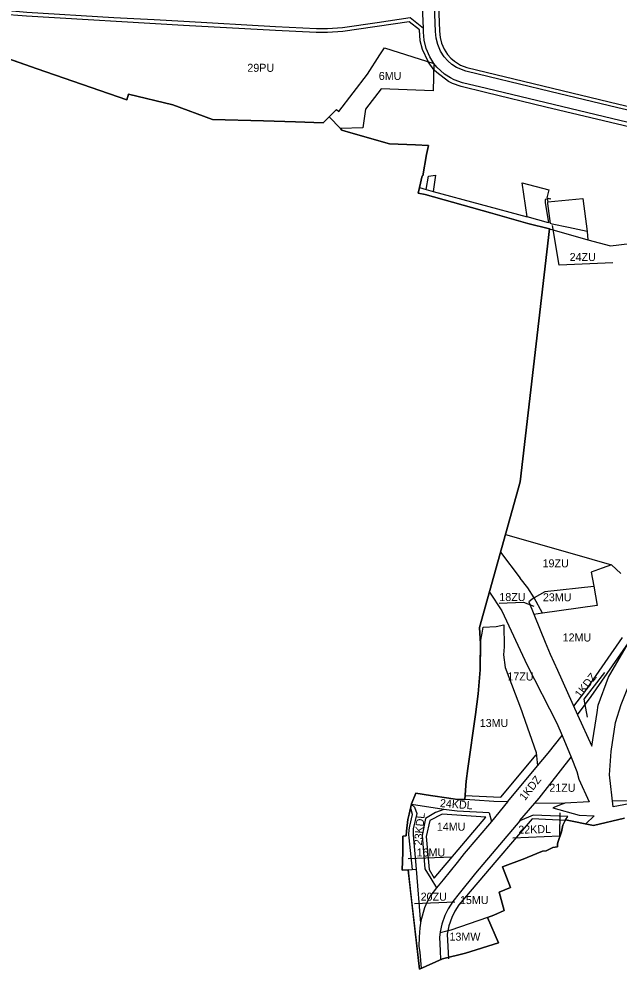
# Model space of a CAD drawing. Extents: x 7428203 to 7432868, y 5542672 to 5545406.
# Drawn here: x 7429842 to 7430591, y 5542672 to 5543859 of the extents above; entities that cross this region are included whole.
import ezdxf

# ---------------------------------------------------------------- set-up
doc = ezdxf.new("R2010")
doc.units = 0
for name, color, linetype in [('__LEGENDA_RAMKA_LOGO_PODZIAŁKA', 7, 'Continuous'), ('_GRANICA_MIASTA', 7, 'Continuous'), ('granicaBulwary', 7, 'Continuous'), ('MPZP_uchwalone_nieobowiazujace jeszcze_SZRAF', 7, 'Continuous')]:
    doc.layers.add(name, color=color, linetype=linetype)

msp = doc.modelspace()

# ---------------------------------------------------------------- linework, layer by layer
at = {"layer": '__LEGENDA_RAMKA_LOGO_PODZIAŁKA'}
msp.add_lwpolyline([(7429769.9, 5543829.3), (7429864.4, 5543796.4), (7429976.3, 5543757.5), (7429978.3, 5543764.7), (7430033.9, 5543751.4), (7430083.2, 5543733.1), (7430146.9, 5543731.4), (7430186.8, 5543730.4), (7430221.5, 5543728.9), (7430229.1, 5543736.5), (7430243.1, 5543721.7), (7430245, 5543719.7), (7430256.1, 5543716.5), (7430304.3, 5543702.6), (7430336.9, 5543701.6), (7430352.9, 5543700.5), (7430350.6, 5543689.3), (7430346.2, 5543662.7), (7430345.1, 5543662.8), (7430341.7, 5543648.1), (7430340.1, 5543641), (7430349, 5543639.5), (7430430.7, 5543616.6), (7430477.2, 5543603.4), (7430504.1, 5543596.7), (7430467.5, 5543280.8), (7430416.9, 5543098.6), (7430417.9, 5543078.3), (7430417.7, 5543045.7), (7430415.2, 5543016), (7430411.8, 5542990), (7430402.4, 5542922.5), (7430400.2, 5542906.8), (7430398.4, 5542883.9), (7430389.4, 5542884.1), (7430378.4, 5542885.7), (7430355.4, 5542888.8), (7430337.2, 5542891.8), (7430332, 5542878.5), (7430328.8, 5542865.5), (7430327.2, 5542858.9), (7430325.7, 5542844.5), (7430325.2, 5542838.8), (7430320.9, 5542838.3), (7430321, 5542818), (7430320.3, 5542795.7), (7430327.5, 5542796.3), (7430330.7, 5542768.7), (7430341.9, 5542672.3), (7430370.6, 5542685.1), (7430399.3, 5542692), (7430440.6, 5542705), (7430426.7, 5542736.6), (7430434.5, 5542739.6), (7430447.7, 5542745.4), (7430441.2, 5542768.3), (7430455.6, 5542774), (7430445.6, 5542800.1), (7430473.5, 5542810.5), (7430476.2, 5542811.4), (7430495.4, 5542819.3), (7430500.2, 5542820), (7430508.5, 5542824.1), (7430514.3, 5542825), (7430514.4, 5542828.3), (7430514.6, 5542830.1), (7430519.4, 5542843.5), (7430520.9, 5542851.8), (7430524.4, 5542858.4), (7430559.4, 5542851.4), (7430598.1, 5542860.7)], dxfattribs=at)
at = {"layer": '_GRANICA_MIASTA'}
for p, q in [((7430361.9, 5543843.2), (7430359.2, 5543909.5)), ((7430346.9, 5543842.2), (7430346.7, 5543847.3)), ((7430347.8, 5543832.2), (7430346.9, 5543842.2)), ((7430362.6, 5543834.7), (7430361.9, 5543843.2)), ((7429864.4, 5543796.4), (7429769.9, 5543829.3)), ((7430350.3, 5543822), (7430347.8, 5543832.2)), ((7430364.6, 5543826.8), (7430362.6, 5543834.7)), ((7430368.2, 5543818.4), (7430364.6, 5543826.8)), ((7430277, 5543789.8), (7430292.1, 5543814)), ((7430292.1, 5543814), (7430298.2, 5543822.7)), ((7430298.2, 5543822.7), (7430359.6, 5543803.1)), ((7430354.9, 5543811.3), (7430350.3, 5543822)), ((7430372.8, 5543811.3), (7430368.2, 5543818.4)), ((7430359.6, 5543803.1), (7430354.9, 5543811.3)), ((7430359.6, 5543803.1), (7430358.9, 5543768.8)), ((7430363.6, 5543798.4), (7430359.6, 5543803.1)), ((7430377.4, 5543806.2), (7430372.8, 5543811.3)), ((7430382.3, 5543801.8), (7430377.4, 5543806.2)), ((7430388.2, 5543797.9), (7430382.3, 5543801.8)), ((7429976.3, 5543757.5), (7429864.4, 5543796.4)), ((7430240.9, 5543743.2), (7430277, 5543789.8)), ((7430373.2, 5543789.9), (7430363.6, 5543798.4)), ((7430380.5, 5543785), (7430373.2, 5543789.9)), ((7430399.7, 5543793.4), (7430388.2, 5543797.9)), ((7430429, 5543786.3), (7430399.7, 5543793.4)), ((7430385.2, 5543782.5), (7430380.5, 5543785)), ((7430395.5, 5543779), (7430385.2, 5543782.5)), ((7430425.5, 5543771.7), (7430395.5, 5543779)), ((7430504.5, 5543768), (7430429, 5543786.3)), ((7430293.8, 5543771.6), (7430274.4, 5543745.9)), ((7430358.9, 5543768.8), (7430293.8, 5543771.6)), ((7430583.4, 5543733.8), (7430425.5, 5543771.7)), ((7430589.7, 5543747.6), (7430504.5, 5543768)), ((7429978.3, 5543764.7), (7429976.3, 5543757.5)), ((7430033.9, 5543751.4), (7429978.3, 5543764.7)), ((7430083.2, 5543733.1), (7430033.9, 5543751.4)), ((7430229.1, 5543736.5), (7430238, 5543745.8)), ((7430238, 5543745.8), (7430240.9, 5543743.2)), ((7430274.4, 5543745.9), (7430271.2, 5543722.6)), ((7430715.2, 5543717.9), (7430589.7, 5543747.6)), ((7430146.9, 5543731.4), (7430083.2, 5543733.1)), ((7430186.8, 5543730.4), (7430146.9, 5543731.4)), ((7430221.5, 5543728.9), (7430186.8, 5543730.4)), ((7430229.1, 5543736.5), (7430221.5, 5543728.9)), ((7430243.1, 5543721.7), (7430229.1, 5543736.5)), ((7430710, 5543703.7), (7430583.4, 5543733.8)), ((7430271.2, 5543722.6), (7430243.1, 5543721.7)), ((7430245, 5543719.7), (7430243.1, 5543721.7)), ((7430256.1, 5543716.5), (7430245, 5543719.7)), ((7430304.3, 5543702.6), (7430256.1, 5543716.5)), ((7430336.9, 5543701.6), (7430304.3, 5543702.6)), ((7430352.9, 5543700.5), (7430336.9, 5543701.6)), ((7430350.6, 5543689.3), (7430352.9, 5543700.5)), ((7430346.2, 5543662.7), (7430350.6, 5543689.3)), ((7430341.7, 5543648.1), (7430345.1, 5543662.8)), ((7430345.1, 5543662.8), (7430346.2, 5543662.7)), ((7430340.1, 5543641), (7430341.7, 5543648.1)), ((7430341.7, 5543648.1), (7430350.2, 5543645.8)), ((7430476.2, 5543611.4), (7430470, 5543654.2)), ((7430470, 5543654.2), (7430503.3, 5543645.2)), ((7430349, 5543639.5), (7430340.1, 5543641)), ((7430430.7, 5543616.6), (7430349, 5543639.5)), ((7430350.2, 5543645.8), (7430358.9, 5543643.4)), ((7430358.9, 5543643.4), (7430476.2, 5543611.4)), ((7430503.3, 5543645.2), (7430500.8, 5543635.3)), ((7430500.8, 5543635.3), (7430505.8, 5543634)), ((7430505.8, 5543634), (7430501.2, 5543633.6)), ((7430501.2, 5543633.6), (7430502, 5543630.2)), ((7430502, 5543630.2), (7430545.9, 5543634.4)), ((7430545.9, 5543634.4), (7430551.5, 5543593.1)), ((7430477.2, 5543603.4), (7430430.7, 5543616.6)), ((7430504.1, 5543596.7), (7430477.2, 5543603.4)), ((7430467.5, 5543280.8), (7430504.1, 5543596.7)), ((7430504.1, 5543596.7), (7430552.3, 5543582.7)), ((7430551.5, 5543593.1), (7430552.3, 5543582.7)), ((7430580.6, 5543575.3), (7430686.2, 5543588.6)), ((7430552.3, 5543582.7), (7430580.6, 5543575.3)), ((7430416.9, 5543098.6), (7430467.5, 5543280.8)), ((7430449.3, 5543215.1), (7430532.7, 5543191.3)), ((7430443.1, 5543192.9), (7430467.7, 5543160.5)), ((7430570, 5543172.7), (7430556.4, 5543168)), ((7430581.9, 5543176.9), (7430570, 5543172.7)), ((7430556.4, 5543168), (7430559.5, 5543150.3)), ((7430559.5, 5543150.1), (7430498.4, 5543143.4)), ((7430429.3, 5543143), (7430444.6, 5543119.7)), ((7430498.4, 5543143.4), (7430485.2, 5543135.9)), ((7430482.2, 5543133.9), (7430478.5, 5543130.8)), ((7430478.5, 5543130.8), (7430499, 5543080.5)), ((7430485.2, 5543135.9), (7430482.2, 5543133.9)), ((7430495.6, 5543116.6), (7430485.3, 5543135.9)), ((7430444.6, 5543119.7), (7430476.4, 5543051.9)), ((7430495.5, 5543116.7), (7430484.8, 5543115.2)), ((7430417.9, 5543078.3), (7430416.9, 5543098.6)), ((7430417.7, 5543048.3), (7430417.9, 5543078.3)), ((7430499, 5543080.5), (7430505.2, 5543065.3)), ((7430505.2, 5543065.3), (7430514.2, 5543045.5)), ((7430415.2, 5543016), (7430417.6, 5543045.3)), ((7430448.7, 5543049), (7430469.2, 5542995)), ((7430476.4, 5543051.9), (7430513.6, 5542979.4)), ((7430514.2, 5543045.5), (7430539.2, 5542989.9)), ((7430411.8, 5542990), (7430415.2, 5543016)), ((7430402.4, 5542922.5), (7430411.8, 5542990)), ((7430513.6, 5542979.4), (7430520.1, 5542963.9)), ((7430520.1, 5542963.9), (7430531.2, 5542936.9)), ((7430487.5, 5542942.7), (7430489.3, 5542925.9)), ((7430400.2, 5542906.8), (7430402.4, 5542922.5)), ((7430398.4, 5542883.9), (7430400.2, 5542906.8)), ((7430332, 5542878.5), (7430337.2, 5542891.8)), ((7430337.2, 5542891.8), (7430355.4, 5542888.8)), ((7430355.4, 5542888.8), (7430378.4, 5542885.7)), ((7430328.8, 5542865.5), (7430332, 5542878.5)), ((7430378.4, 5542885.7), (7430389.4, 5542884.1)), ((7430389.4, 5542884.1), (7430398.4, 5542883.9)), ((7430411, 5542883.1), (7430398.4, 5542883.9)), ((7430434.7, 5542881.5), (7430411, 5542883.1)), ((7430451.8, 5542881), (7430431.9, 5542856.6)), ((7430451.8, 5542881), (7430434.7, 5542881.5)), ((7430486.4, 5542880), (7430523.2, 5542879.2)), ((7430327.2, 5542858.9), (7430328.8, 5542865.5)), ((7430361.9, 5542867.6), (7430349.2, 5542860.3)), ((7430372.1, 5542871.5), (7430361.9, 5542867.6)), ((7430388.7, 5542869.2), (7430372.1, 5542871.5)), ((7430428.8, 5542867.3), (7430388.7, 5542869.2)), ((7430527.1, 5542862.6), (7430483.9, 5542864.6)), ((7430325.7, 5542844.5), (7430327.2, 5542858.9)), ((7430349.2, 5542860.3), (7430345, 5542839.1)), ((7430524.4, 5542858.4), (7430520.9, 5542851.8)), ((7430524.4, 5542858.4), (7430527.1, 5542862.6)), ((7430559.4, 5542851.4), (7430524.4, 5542858.4)), ((7430598.1, 5542860.7), (7430559.4, 5542851.4)), ((7430325.2, 5542838.8), (7430325.7, 5542844.5)), ((7430519.4, 5542843.5), (7430514.6, 5542830.1)), ((7430520.9, 5542851.8), (7430519.4, 5542843.5)), ((7430320.9, 5542838.3), (7430325.2, 5542838.8)), ((7430321, 5542818), (7430320.9, 5542838.3)), ((7430345, 5542839.1), (7430348.6, 5542797.6)), ((7430514.6, 5542830.1), (7430514.4, 5542828.3)), ((7430320.3, 5542795.7), (7430321, 5542818)), ((7430495.4, 5542819.3), (7430476.2, 5542811.4)), ((7430500.2, 5542820), (7430495.4, 5542819.3)), ((7430508.5, 5542824.1), (7430500.2, 5542820)), ((7430514.3, 5542825), (7430508.5, 5542824.1)), ((7430514.4, 5542828.3), (7430514.3, 5542825)), ((7430473.5, 5542810.5), (7430445.6, 5542800.1)), ((7430476.2, 5542811.4), (7430473.5, 5542810.5)), ((7430327.5, 5542796.3), (7430320.3, 5542795.7)), ((7430327.5, 5542796.3), (7430337.7, 5542796.8)), ((7430330.5, 5542770.7), (7430327.5, 5542796.3)), ((7430337.7, 5542796.8), (7430343, 5542729.4)), ((7430348.6, 5542797.6), (7430355.9, 5542785.4)), ((7430445.6, 5542800.1), (7430455.6, 5542774)), ((7430355.9, 5542785.4), (7430363.2, 5542773.5)), ((7430341.9, 5542672.3), (7430330.5, 5542770.7)), ((7430455.6, 5542774), (7430441.2, 5542768.3)), ((7430441.2, 5542768.3), (7430447.7, 5542745.4)), ((7430434.5, 5542739.6), (7430426.7, 5542736.6)), ((7430426.7, 5542736.6), (7430440.6, 5542705)), ((7430447.7, 5542745.4), (7430434.5, 5542739.6)), ((7430440.6, 5542705), (7430399.3, 5542692)), ((7430342.3, 5542692.8), (7430344.1, 5542673.3)), ((7430367.5, 5542695.6), (7430368, 5542683.9)), ((7430399.3, 5542692), (7430370.6, 5542685.1)), ((7430370.6, 5542685.1), (7430341.9, 5542672.3))]:
    msp.add_line(p, q, dxfattribs=at)
for points in [[(7429692.7, 5543891.1), (7429733.7, 5543881.8), (7429787.1, 5543873), (7429851.1, 5543867.3), (7429960.1, 5543860.7), (7429984.9, 5543859.3), (7430010.5, 5543857.9), (7430047.5, 5543855.8), (7430162, 5543849.3), (7430213.1, 5543846.6), (7430226.8, 5543846.7), (7430245.5, 5543848.2), (7430288.9, 5543854.4), (7430330.3, 5543860.4), (7430346.7, 5543847.3), (7430344.8, 5543892.7)], [(7430350.2, 5543645.8), (7430352.9, 5543662.2), (7430361.9, 5543663.7), (7430358.9, 5543643.4)], [(7430501.2, 5543633.6), (7430498.7, 5543633.4), (7430499, 5543629.5), (7430503, 5543603.9), (7430476.2, 5543611.4)], [(7430551.5, 5543593.1), (7430528.1, 5543598.2), (7430507.4, 5543602.6), (7430505.4, 5543603.2), (7430502.2, 5543628.1), (7430502, 5543630.2)], [(7430532.7, 5543191.3), (7430581.9, 5543176.9), (7430593.2, 5543166)], [(7430485.2, 5543135.9), (7430477, 5543148.5), (7430467.7, 5543160.5)], [(7430559.5, 5543150.3), (7430563.8, 5543126.3), (7430495.6, 5543116.6)], [(7430417.6, 5543045.3), (7430417.7, 5543048.3), (7430418.2, 5543080.7), (7430420, 5543091.5), (7430421.2, 5543099.1), (7430437.6, 5543100), (7430447, 5543102.2), (7430447.6, 5543074.7)], [(7430539.2, 5542989.9), (7430556.3, 5543012.6), (7430602.9, 5543079.6)], [(7430539.2, 5542989.9), (7430557.2, 5542950.5), (7430563.6, 5542992.8), (7430565, 5543001.7), (7430578, 5543036.9), (7430602.9, 5543079.6)], [(7430447.6, 5543074.7), (7430446.9, 5543064.8), (7430448.7, 5543049)], [(7430469.2, 5542995), (7430470.9, 5542990.1), (7430487.5, 5542942.7)], [(7430489.3, 5542925.9), (7430502.4, 5542941.8), (7430520.1, 5542963.9)], [(7430467.3, 5542857.6), (7430491.3, 5542885.8), (7430531.2, 5542936.9)], [(7430531.2, 5542936.9), (7430538.6, 5542919), (7430540.8, 5542909.2), (7430554, 5542881.2), (7430523.2, 5542879.2), (7430519.9, 5542878), (7430508.6, 5542873.7), (7430541.5, 5542864.3), (7430560.1, 5542863.7), (7430549.5, 5542853.4)], [(7430451.8, 5542881), (7430468.8, 5542901.3), (7430489.3, 5542925.9)], [(7430372.1, 5542871.5), (7430331.9, 5542877.9)], [(7430331.8, 5542877.8), (7430335.8, 5542874.2), (7430338.6, 5542866.4), (7430333.9, 5542847.2), (7430333.8, 5542839.7), (7430337.7, 5542797.1), (7430337.7, 5542796.8)], [(7430428.8, 5542867.3), (7430431.9, 5542856.6), (7430397.6, 5542816.5), (7430388.9, 5542805.5), (7430380.1, 5542794.6), (7430371.3, 5542783.7), (7430363.2, 5542773.5), (7430356.1, 5542764.4), (7430350.8, 5542755.4), (7430348.3, 5542748.8), (7430343.4, 5542732.5), (7430342.2, 5542723.9), (7430341.3, 5542712.1), (7430341.2, 5542701), (7430342.3, 5542692.8)], [(7430483.9, 5542864.6), (7430467.2, 5542857.5), (7430411.9, 5542791.9), (7430391.2, 5542766.4), (7430383.3, 5542756.6), (7430377.7, 5542747.3), (7430373.5, 5542739), (7430369.8, 5542728.5), (7430367.8, 5542718.8), (7430367, 5542711.5), (7430367.5, 5542695.6)], [(7430426.7, 5542736.6), (7430380.8, 5542720.6), (7430367.6, 5542717.4)]]:
    msp.add_lwpolyline(points, dxfattribs=at)
msp.add_lwpolyline([(7430802.2, 5542918.5), (7430613.6, 5542879.6), (7430603.7, 5542878.4), (7430583.9, 5542874.9), (7430579.2, 5542914.6), (7430581.3, 5542943.8), (7430586.6, 5542980), (7430593.7, 5543002.6), (7430602.2, 5543023.3), (7430618.7, 5543052), (7430623.3, 5543059.9), (7430640, 5543078.8), (7430655, 5543090.3), (7430667.3, 5543085), (7430803.3, 5542928.2)], close=True, dxfattribs=at)
at = {"layer": 'granicaBulwary'}
for p, q in [((7430327.6, 5542810.1), (7430382.7, 5542812.3)), ((7430335.4, 5542754.1), (7430385.9, 5542756.2))]:
    msp.add_line(p, q, dxfattribs=at)
for points in [[(7430583.4, 5543554), (7430516.4, 5543551.3), (7430507.9, 5543600.7)], [(7430441.3, 5543129.2), (7430471.7, 5543130.4), (7430484.5, 5543125.3)], [(7430572.9, 5543042.4), (7430547.2, 5543009.3), (7430551.5, 5542986.6)], [(7430458.5, 5542836.1), (7430517.2, 5542838.5), (7430517.4, 5542867.4)]]:
    msp.add_lwpolyline(points, dxfattribs=at)
at = {"layer": 'MPZP_uchwalone_nieobowiazujace jeszcze_SZRAF'}
for p, q in [((7430443.6, 5542886.8), (7430487.7, 5542939.6)), ((7430398.4, 5542888.9), (7430443.6, 5542886.8)), ((7430424.8, 5542862.1), (7430370, 5542865.5)), ((7430360.3, 5542785.8), (7430424.8, 5542862.1))]:
    msp.add_line(p, q, dxfattribs=at)
for points in [[(7430364.2, 5543909.9), (7430366.9, 5543843.5), (7430367.5, 5543835.5), (7430369.3, 5543828.4), (7430372.6, 5543820.8), (7430376.8, 5543814.4), (7430380.9, 5543809.7), (7430385.4, 5543805.8), (7430393.2, 5543800.9), (7430401.1, 5543798.2), (7430590.9, 5543752.4), (7430800.1, 5543703), (7430877.2, 5543684.2), (7430886.6, 5543682.5), (7430893.5, 5543682.2), (7430916.9, 5543684.3), (7430970.6, 5543689.2), (7431085, 5543701.7), (7431096.6, 5543746), (7431141.1, 5543916.6)], [(7430352.6, 5543805.4), (7430345.6, 5543820.4), (7430342.8, 5543831.4), (7430341.8, 5543844.9), (7430329, 5543855.1), (7430246.1, 5543843.2), (7430226.9, 5543841.7), (7430212.9, 5543841.6), (7430161.8, 5543844.3), (7430047.2, 5543850.5), (7429850.8, 5543862.3), (7429817.8, 5543864.6), (7429787.5, 5543867.6), (7429750, 5543873.6), (7429700.2, 5543884)], [(7431065.4, 5543628.4), (7431071.5, 5543651.7), (7431064.4, 5543654.8), (7431057.5, 5543662.5), (7431054, 5543671.8), (7431053.9, 5543673.2), (7430976.8, 5543664.8), (7430904.4, 5543658.1), (7430893.9, 5543657.1), (7430886.7, 5543657.2), (7430879, 5543658.2), (7430832.7, 5543669.6), (7430708.9, 5543698.9), (7430499.8, 5543748.5), (7430424.3, 5543766.8), (7430394.1, 5543774.2), (7430383.2, 5543777.9), (7430377.9, 5543780.7), (7430363.4, 5543791.8), (7430360, 5543794.9), (7430352.7, 5543805.2)], [(7430534.6, 5543000.4), (7430548.2, 5543018.5), (7430595.5, 5543086.3)], [(7430582.7, 5542882.4), (7430604.4, 5542882.9), (7430646.9, 5542890.7), (7430761.2, 5542915.2), (7430797.4, 5542922.7), (7430798.1, 5542926.5), (7430768.5, 5542960.7), (7430729.6, 5543005.6), (7430675, 5543068.5), (7430662.1, 5543083.4)], [(7430332.9, 5542796.5), (7430329.1, 5542836), (7430328.5, 5542840.3), (7430328.9, 5542846.3), (7430329.6, 5542850.8), (7430333.2, 5542865.3), (7430331.5, 5542871.4), (7430330.7, 5542873.4)], [(7430370, 5542865.5), (7430354.8, 5542857.8), (7430350.2, 5542837.9), (7430354, 5542796.4), (7430360.3, 5542785.8)], [(7430524.5, 5542857.8), (7430482.6, 5542859.8), (7430438.5, 5542808.4), (7430391, 5542752.4), (7430386, 5542744.7), (7430382.1, 5542736.6), (7430378.6, 5542726.4), (7430376.6, 5542715.9), (7430378, 5542684.8)]]:
    msp.add_lwpolyline(points, dxfattribs=at)

# ---------------------------------------------------------------- texts
at = {"layer": 'granicaBulwary'}
for s, p in [('29PU', (7430126.8, 5543792.7)), ('6MU', (7430291, 5543782.5)), ('24ZU', (7430529.4, 5543556.4)), ('19ZU', (7430495.6, 5543173.9)), ('18ZU', (7430441.6, 5543131.8)), ('23MU', (7430496, 5543131.5)), ('12MU', (7430520.7, 5543081.3)), ('17ZU', (7430451.6, 5543032.6)), ('13MU', (7430417.1, 5542974.5)), ('21ZU', (7430504, 5542893.6)), ('14MU', (7430363.5, 5542845)), ('16MU', (7430338.2, 5542812.8)), ('20ZU', (7430343.3, 5542757.6)), ('15MU', (7430392.4, 5542753.4)), ('13MW', (7430379.3, 5542707.7))]:
    msp.add_text(s, height=10, dxfattribs=at).set_placement(p)
for s, rotation, p in [('1KDZ', 51.8677, (7430542.7, 5543010)), ('1KDZ', 51.8446, (7430473.5, 5542881.8)), ('24KDL', 355.7812, (7430367.1, 5542874.6)), ('23KDL', 84.5311, (7430344.7, 5542826.3)), ('22KDL', 1.5505, (7430465.4, 5542841.2))]:
    msp.add_text(s, height=10, rotation=rotation, dxfattribs=at).set_placement(p)

doc.saveas('drawing.dxf')
